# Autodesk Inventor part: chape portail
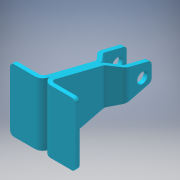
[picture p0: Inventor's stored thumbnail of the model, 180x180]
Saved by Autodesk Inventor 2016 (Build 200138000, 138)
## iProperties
Shininess: 20.0
Length Units: 11269
Angle Units: 11279
Time Units: 11290
Mass Units: 11283
Length Display Precision: 3
Angle Display Precision: 2
Compacted: True
Created: 2002-09
Part Number: chape portail
Material: Acier
Document SubType Name: Modélisation
Designer: thchene
Mass: 154.343 g
Surface Area: 119.93 cm^2
Volume: 19.6616 cm^3
Density: 7.85 g/cm^3
Appearance: Bleu (ciel - vif)
Density: 0.0
Volumn: 0.0
Area: 0.0
PropertySet Name: Model Information
Control State: 0
Master: False
Checked Out: False
Author: thchene
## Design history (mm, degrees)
sketch "Esquisse1"
  geometry: L1 (-19.94, 57.736)-(-19.94, 39.736); L2 (-19.94, 39.736)-(-11.94, 30.736); L3 (-11.94, 30.736)-(-11.94, -14.264); L4 (-11.94, -14.264)-(-36.94, -14.264); L5 (-36.94, -11.264)-(-14.94, -11.264); L6 (-14.94, -11.264)-(-14.94, 29.595); L7 (-14.94, 29.595)-(-22.94, 38.595); L8 (-22.94, 38.595)-(-22.94, 57.736); L9 (-22.94, 57.736)-(-19.94, 57.736); L10 (-36.94, -11.264)-(-36.94, -14.264)
  constraints: 20 end point, 4 perpendicular, 2 vertical, 3 other
  dimensions: "d0" = 25 distance of L3.end L4.end; "d1" = 45 distance of L2.end L3.end; "d2" = 54 distance from line of L4 L1.end; "d3" = 72 distance from line of L4 L1.start; "d4" = 3 distance between parallel lines of L4 L5; "d15" = 8 distance between parallel lines of L3 L1
extrude "Extrusion1" new body sketch "Esquisse1" distance "d5" = 48; taper "d6" = 0 deg
sketch "Esquisse3"
  geometry: L1 (-48, 45)-(-48, 0) reference; L2 (0, 45)-(-48, 45) reference; L3 (-31, 72)-(-48, 72); L4 (-48, 72)-(-48, 4); L5 (-48, 4)-(-31, 72); L6 (0, 72)-(-48, 72) reference; L7 (0, 45)-(0, 0) reference; L8 (-17, 72)-(0, 72); L9 (0, 72)-(0, 4); L10 (0, 4)-(-17, 72)
  constraints: 12 end point, 4 collinear, 3 perpendicular, 1 parallel
  dimensions: "d9" = 17 distance of L3.start L3.end; "d10" = 68 distance of L3.end L4.end; "d13" = 17 distance of L8.start L8.end (= d9); "d14" = 68 distance of L8.end L9.end (= d10)
extrude "Extrusion2" cut sketch "Esquisse3" stored distance "d11" = 48; taper "d12" = 0 deg
fillet "Congé1" dims "d16" = 3, "d17" = 6
sketch "Esquisse4"
  geometry: L1 (-17, -72)-(31, -72) reference; L2 (-17, -72)-(-17, -69) reference; 1 further point
  dimensions: "d18" = 65 distance from line of L1 point (8, -7); "d19" = 25 distance from line of point (8, -7) L2
hole "Perçage1" sketch "Esquisse4" at (8, -7) diameter "d20" = 8; stored, may be unused: countersink angle "d24" = 82 deg, drill point angle "d26" = 118 deg; dims "d21" = 6, "d22" = 4, "d23" = 2, "d25" = 8
fillet "Congé2" dims "d27" = 3
mirror "Symétrie1"
node "Solide1"
node "Corps solides"
node "Corps surfaciques"
